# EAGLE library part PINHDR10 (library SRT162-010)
pinheader/pinsocket 1x10
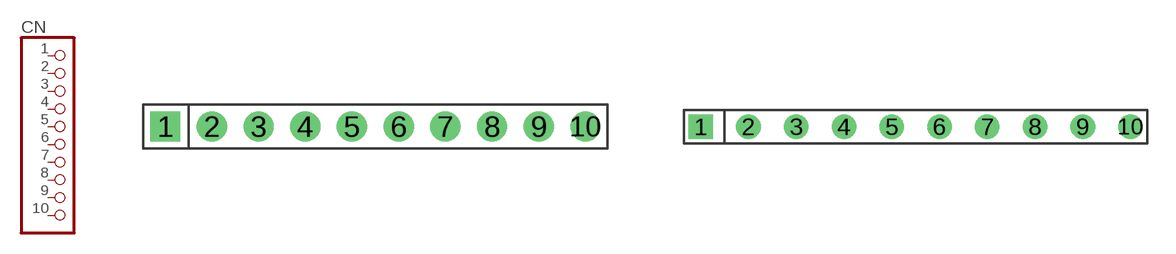
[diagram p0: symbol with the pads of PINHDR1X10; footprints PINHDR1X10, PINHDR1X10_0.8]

Designator prefix CN

## PINHDR10  [PINHDR1X10]
1  1  pas
2  2  pas
3  3  pas
4  4  pas
5  5  pas
6  6  pas
7  7  pas
8  8  pas
9  9  pas
10  10  pas

## PINHDR100.8  [PINHDR1X10_0.8]
Pads as for PINHDR1X10

## PINHDR101.28  [CONN-005INX10]
Pads as for PINHDR1X10

## PINHDR102X5  [PINHDR2X5]
Pads as for PINHDR1X10

## PINHDR102MM  [PINHDR1X10_2MM]
Pads as for PINHDR1X10

## PINHDR101.27MM  [PINHDR1X10_1.27MM]
Pads as for PINHDR1X10

## PINHDR10_2X5_2MM  [PINHDR2X5_2MM]
Pads as for PINHDR1X10

## Footprint PINHDR1X10 (pad centres in mm)
drill 1.1 square: 1 -11.43,0
drill 1.1 round: 2 -8.89,0; 3 -6.35,0; 4 -3.81,0; 5 -1.27,0; 6 1.27,0; 7 3.81,0; 8 6.35,0; 9 8.89,0; 10 11.43,0

## Footprint PINHDR1X10_0.8 (pad centres in mm)
drill 0.8 square: 1 -11.43,0
drill 0.8 round: 2 -8.89,0; 3 -6.35,0; 4 -3.81,0; 5 -1.27,0; 6 1.27,0; 7 3.81,0; 8 6.35,0; 9 8.89,0; 10 11.43,0

## Footprint CONN-005INX10 (pad centres in mm)
smd 0.635 x 1.905: 1 -5.08,0; 2 -3.81,0; 3 -2.54,0; 4 -1.27,0; 5 0,0; 6 1.27,0; 7 2.54,0; 8 3.81,0; 9 5.08,0; 10 6.35,0

## Footprint PINHDR2X5 (pad centres in mm)
drill 1.1 square: 1 -5.08,-1.27
drill 1.1 round: 2 -5.08,1.27; 3 -2.54,-1.27; 4 -2.54,1.27; 5 0,-1.27; 6 0,1.27; 7 2.54,-1.27; 8 2.54,1.27; 9 5.08,-1.27; 10 5.08,1.27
